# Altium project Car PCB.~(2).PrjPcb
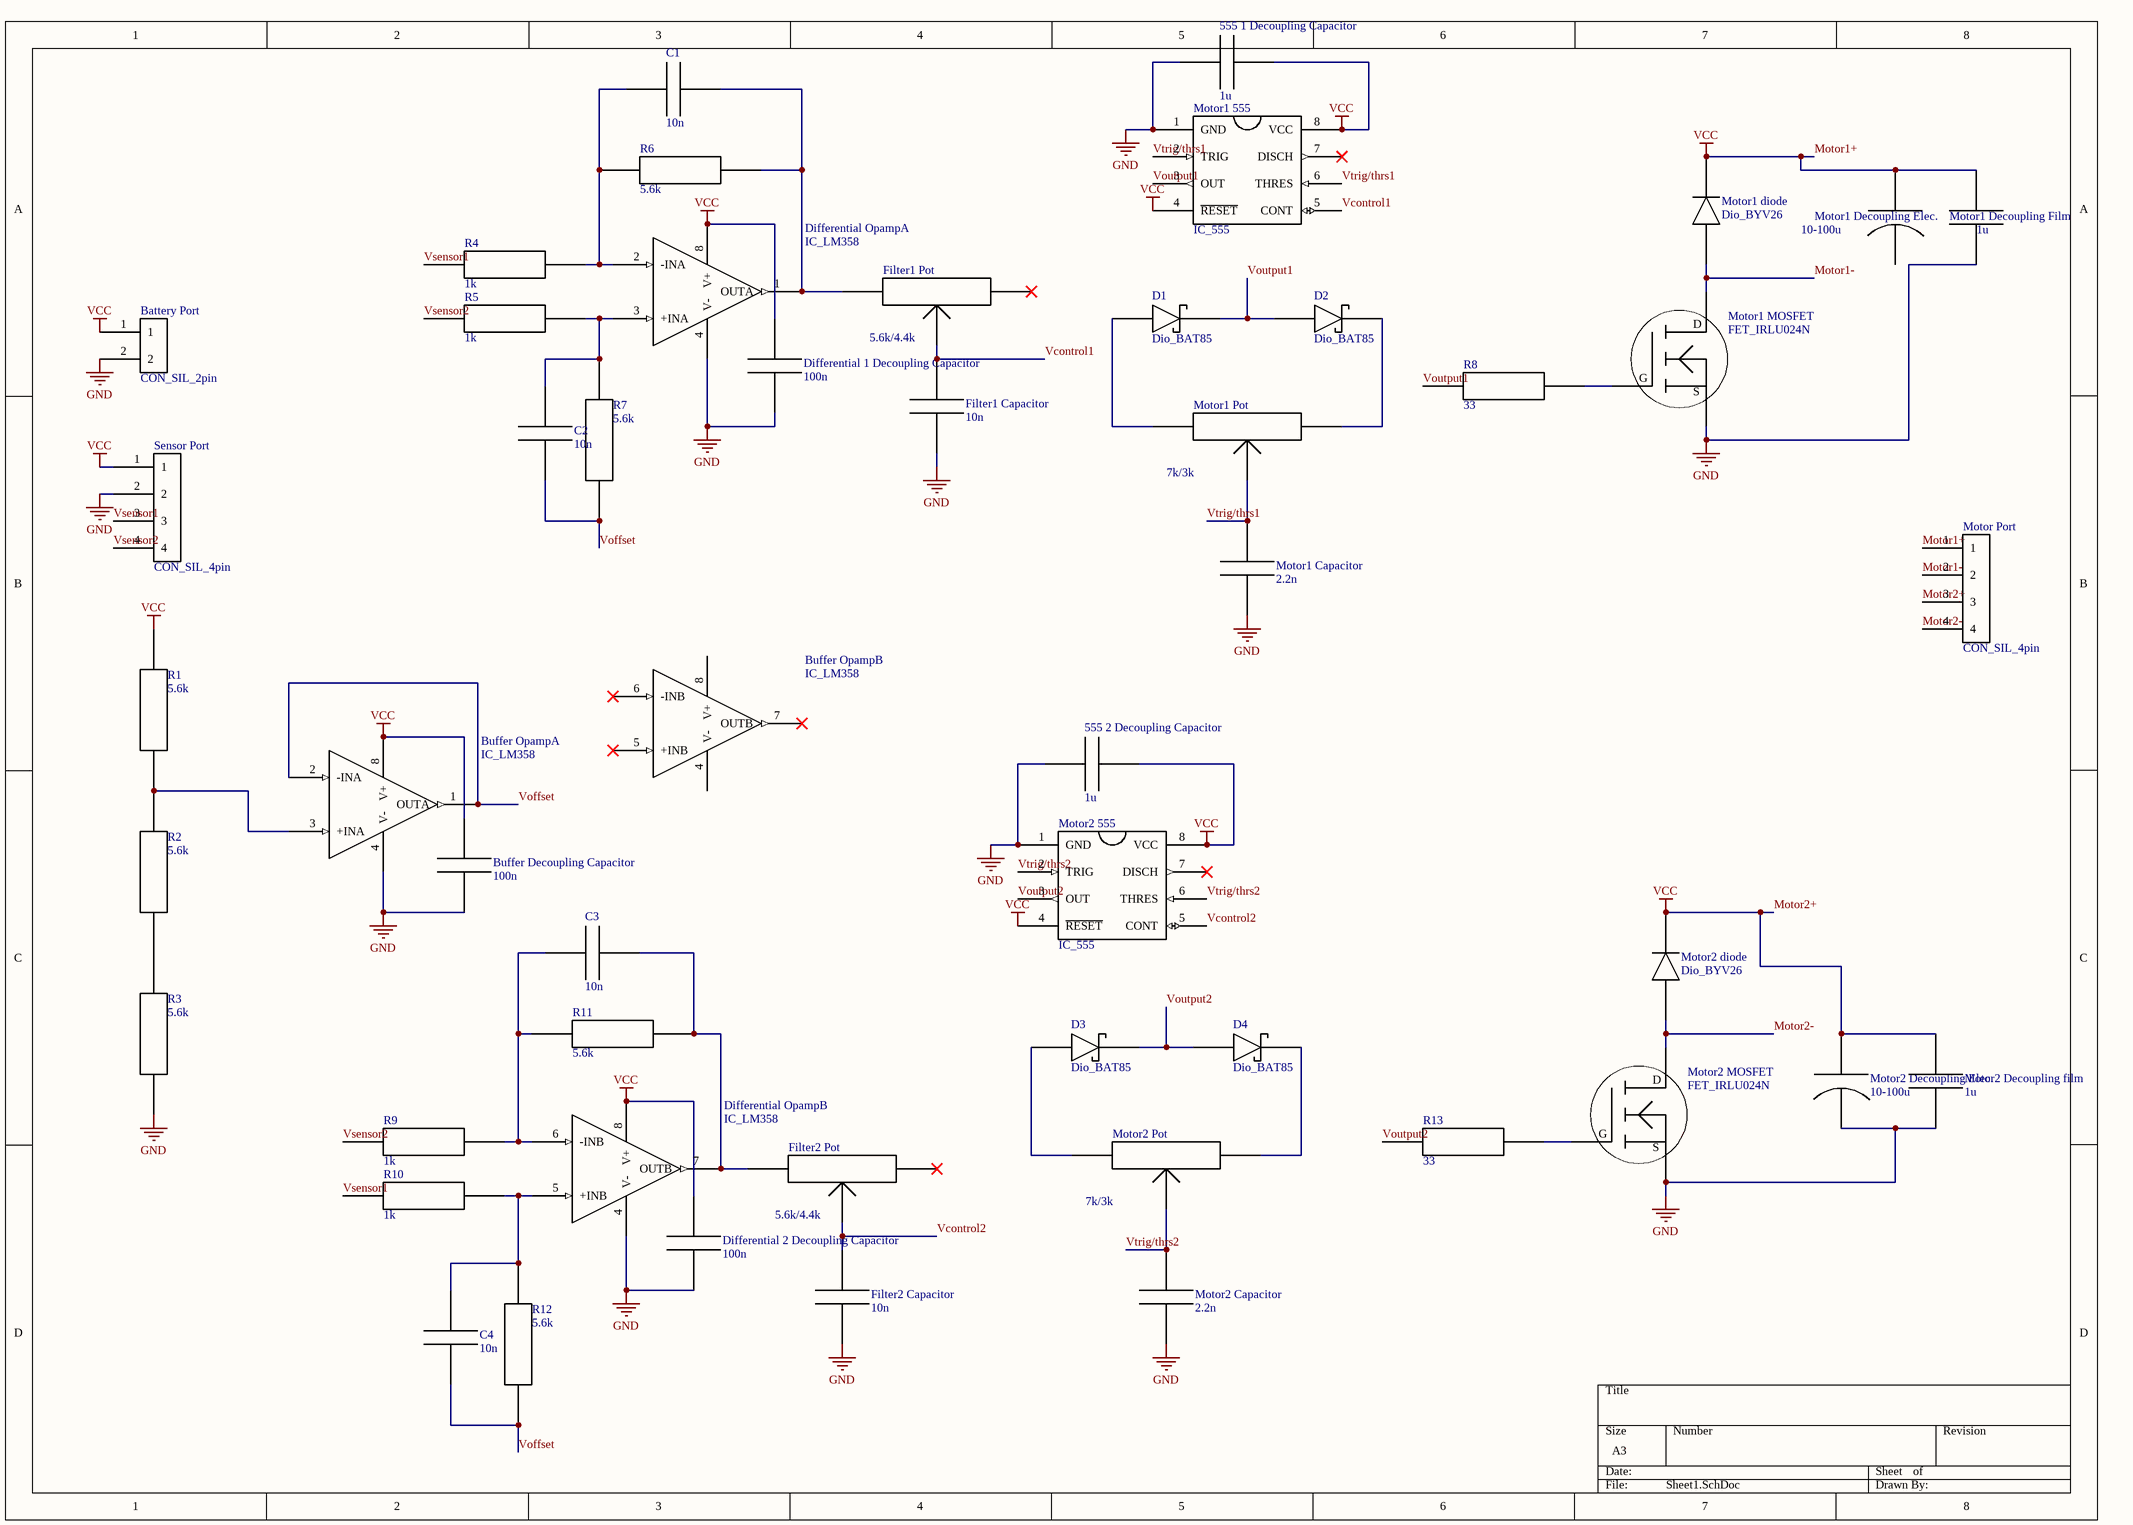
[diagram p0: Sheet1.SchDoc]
1 sheet, 49 parts. Net scope: global (net labels, ports and power ports of the same name join across sheets).
Board file: PCB1.PcbDoc

## Sheet Sheet1.SchDoc
size A3

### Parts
555_1_Decoupling_Capacitor  1u  [CAP_FILM_3.2mm]
555_2_Decoupling_Capacitor  1u  [CAP_FILM_3.2mm]
Battery_Port  CON_SIL_2pin  [ece-HDR1X2]
Buffer_Decoupling_Capacitor  100n  [CAP_FILM_3.2mm]
Buffer_Opamp  IC_LM358  [DIP_8]  (parts A,B of 2)
C1  10n  [CAP_FILM_3.2mm]
C2  10n  [CAP_FILM_3.2mm]
C3  10n  [CAP_FILM_3.2mm]
C4  10n  [CAP_FILM_3.2mm]
D1  Dio_BAT85  [Diode_SmallSignal]
D2  Dio_BAT85  [Diode_SmallSignal]
D3  Dio_BAT85  [Diode_SmallSignal]
D4  Dio_BAT85  [Diode_SmallSignal]
Differential_1_Decoupling_Capacitor  100n  [CAP_FILM_3.2mm]
Differential_2_Decoupling_Capacitor  100n  [CAP_FILM_3.2mm]
Differential_Opamp  IC_LM358  [DIP_8]  (parts A,B of 2)
Filter1_Capacitor  10n  [CAP_FILM_3.2mm]
Filter1_Pot  5.6k/4.4k  [POT]
Filter2_Capacitor  10n  [CAP_FILM_3.2mm]
Filter2_Pot  5.6k/4.4k  [POT]
Motor1_555  IC_555  [DIP_8]
Motor1_Capacitor  2.2n  [CAP_FILM_3.2mm]
Motor1_Decoupling_Elec.  10-100u  [CAP_Electrolytic_6.3mmDiameter]
Motor1_Decoupling_Film  1u  [CAP_FILM_3.2mm]
Motor1_diode  Dio_BYV26  [SOD_47]
Motor1_MOSFET  FET_IRLU024N  [TO_251AA]
Motor1_Pot  7k/3k  [POT]
Motor2_555  IC_555  [DIP_8]
Motor2_Capacitor  2.2n  [CAP_FILM_3.2mm]
Motor2_Decoupling_Elec.  10-100u  [CAP_Electrolytic_6.3mmDiameter]
Motor2_Decoupling_film  1u  [CAP_FILM_3.2mm]
Motor2_diode  Dio_BYV26  [SOD_47]
Motor2_MOSFET  FET_IRLU024N  [TO_251AA]
Motor2_Pot  7k/3k  [POT]
Motor_Port  CON_SIL_4pin  [ece-HDR1X4]
R1  5.6k  [Resistor_400mil_pitch]
R2  5.6k  [Resistor_400mil_pitch]
R3  5.6k  [Resistor_400mil_pitch]
R4  1k  [Resistor_400mil_pitch]
R5  1k  [Resistor_400mil_pitch]
R6  5.6k  [Resistor_400mil_pitch]
R7  5.6k  [Resistor_400mil_pitch]
R8  33  [Resistor_400mil_pitch]
R9  1k  [Resistor_400mil_pitch]
R10  1k  [Resistor_400mil_pitch]
R11  5.6k  [Resistor_400mil_pitch]
R12  5.6k  [Resistor_400mil_pitch]
R13  33  [Resistor_400mil_pitch]
Sensor_Port  CON_SIL_4pin  [ece-HDR1X4]

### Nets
GND: 555_1_Decoupling_Capacitor.1 555_2_Decoupling_Capacitor.1 Battery_Port.2 Buffer_Decoupling_Capacitor.2 Buffer_Opamp.4(V-) Differential_1_Decoupling_Capacitor.2 Differential_2_Decoupling_Capacitor.2 Differential_Opamp.4(V-) Filter1_Capacitor.2 Filter2_Capacitor.2 Motor1_555.1(GND) Motor1_Capacitor.2 Motor1_Decoupling_Film.2 Motor1_MOSFET.3(S) Motor2_555.1(GND) Motor2_Capacitor.2 Motor2_Decoupling_Elec..2 Motor2_Decoupling_film.2 Motor2_MOSFET.3(S) R3.2 Sensor_Port.2
Motor1+: 555_1_Decoupling_Capacitor.2 555_2_Decoupling_Capacitor.2 Battery_Port.1 Buffer_Decoupling_Capacitor.1 Buffer_Opamp.8(V+) Differential_1_Decoupling_Capacitor.1 Differential_2_Decoupling_Capacitor.1 Differential_Opamp.8(V+) Motor1_555.4(~{RESET}) Motor1_555.8(VCC) Motor1_Decoupling_Elec..1 Motor1_Decoupling_Film.1 Motor1_diode.2 Motor2_555.4(~{RESET}) Motor2_555.8(VCC) Motor2_Decoupling_Elec..1 Motor2_Decoupling_film.1 Motor2_diode.2 Motor_Port.1 Motor_Port.3 R1.1 Sensor_Port.1  [also labelled Motor2+, VCC]
Motor1-: Motor1_diode.1 Motor1_MOSFET.1(D) Motor_Port.2
Motor2-: Motor2_diode.1 Motor2_MOSFET.1(D) Motor_Port.4
Vcontrol1: Filter1_Capacitor.1 Filter1_Pot.2 Motor1_555.5(CONT)
Vcontrol2: Filter2_Capacitor.1 Filter2_Pot.2 Motor2_555.5(CONT)
Voffset: Buffer_Opamp.1(OUTA) Buffer_Opamp.2(-INA) C2.1 C4.1 R7.1 R12.1
Voutput1: D1.2 D2.1 Motor1_555.3(OUT) R8.2
Voutput2: D3.2 D4.1 Motor2_555.3(OUT) R13.2
Vsensor1: R4.1 R10.1 Sensor_Port.3
Vsensor2: R5.1 R9.1 Sensor_Port.4
Vtrig/thrs1: Motor1_555.2(TRIG) Motor1_555.6(THRES) Motor1_Capacitor.1 Motor1_Pot.2
Vtrig/thrs2: Motor2_555.2(TRIG) Motor2_555.6(THRES) Motor2_Capacitor.1 Motor2_Pot.2
NetBuffer_Opamp_3: Buffer_Opamp.3(+INA) R1.2 R2.1
NetC1_1: C1.1 Differential_Opamp.2(-INA) R4.2 R6.1
NetC1_2: C1.2 Differential_Opamp.1(OUTA) Filter1_Pot.3 R6.2
NetC2_2: C2.2 Differential_Opamp.3(+INA) R5.2 R7.2
NetC3_1: C3.1 Differential_Opamp.7(OUTB) Filter2_Pot.3 R11.2
NetC3_2: C3.2 Differential_Opamp.6(-INB) R9.2 R11.1
NetC4_2: C4.2 Differential_Opamp.5(+INB) R10.2 R12.2
NetD1_1: D1.1 Motor1_Pot.3
NetD2_2: D2.2 Motor1_Pot.1
NetD3_1: D3.1 Motor2_Pot.3
NetD4_2: D4.2 Motor2_Pot.1
NetMotor1_MOSFET_2: Motor1_MOSFET.2(G) R8.1
NetMotor2_MOSFET_2: Motor2_MOSFET.2(G) R13.1
NetR2_2: R2.2 R3.1

Not connected (* = marked no-connect by the designer): Buffer_Opamp 5(+INB)* 6(-INB)* 7(OUTB)*; Filter1_Pot 1*; Filter2_Pot 1*; Motor1_555 7(DISCH)*; Motor1_Decoupling_Elec. 2; Motor2_555 7(DISCH)*

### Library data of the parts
555_1_Decoupling_Capacitor 555_2_Decoupling_Capacitor Buffer_Decoupling_Capacitor C1-C4 Differential_1_Decoupling_Capacitor Differential_2_Decoupling_Capacitor Filter1_Capacitor Filter2_Capacitor Motor1_Capacitor Motor1_Decoupling_Film Motor2_Capacitor Motor2_Decoupling_film = Cap_Film_Medium: Cap_Ceramic
Battery_Port = CON_SIL_2pin: 2 pin in line connector
Buffer_Opamp Differential_Opamp = IC_LM358: LM358 - Dual Opamp
Filter1_Pot Filter2_Pot Motor1_Pot Motor2_Pot = Res_Pot_10k
Motor1_555 Motor2_555 = IC_555: NEC555
Motor1_Decoupling_Elec. Motor2_Decoupling_Elec. = Cap_Electrolytic
Motor1_diode Motor2_diode = Dio_BYV26: BYV26
Motor1_MOSFET Motor2_MOSFET = FET_IRLU024N: N-Chan MOSFET 55V 17A 65mOhm
Motor_Port Sensor_Port = CON_SIL_4pin: 4 pin in line connector
R1-R13 = Res_0.25W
